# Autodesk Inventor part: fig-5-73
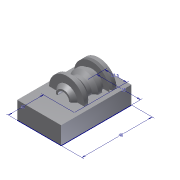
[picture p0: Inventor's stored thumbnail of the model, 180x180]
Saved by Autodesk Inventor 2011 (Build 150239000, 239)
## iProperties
Created: 2010-02
Part Number: fig-5-73
Document SubType Name: Modeling
Designer: CADSoft
Density: 1 g/cm^3
Author: CADSoft
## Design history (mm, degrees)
sketch "Sketch1"
  geometry: L1 (-12.5, 20)-(12.5, 20); L2 (12.5, 20)-(12.5, -20); L3 (12.5, -20)-(-12.5, -20); L4 (-12.5, -20)-(-12.5, 20); 1 further point
  constraints: 8 end point, 2 horizontal, 2 vertical
  dimensions: "d0" = 25 distance of L1.start L1.end; "d1" = 40 distance of L1.end L2.end; "d2" = 20 distance from line of L3 point (0, 0); "d3" = 12.5 distance from line of L4 point (0, 0)
extrude "Extrusion1" new body sketch "Sketch1" distance "d4" = 10; taper "d5" = 0 deg
sketch "Sketch2"
  geometry: L1 (-0.054, -20.11)-(-0.054, 21.401); L2 (3.173, 13.981)-(10.055, 13.981); L3 (10.055, 13.981)-(10.055, 11.83); L4 (10.055, 11.83)-(8.012, 10.969); L5 (8.012, 10.969)-(10.055, 10.001); L6 (10.055, 10.001)-(6.614, 10.001); L7 (6.614, 10.001)-(6.614, 7.851); L8 (6.614, 7.851)-(8.012, 7.851); L9 (8.012, 7.851)-(8.012, 5.7); L10 (8.012, 5.7)-(5.996, 4.073); L11 (5.996, 4.073)-(5.996, 1.828); L12 (5.996, 1.828)-(8.012, -0.069); L13 (8.012, -0.069)-(8.012, -2.151); L14 (8.012, -2.151)-(10.055, -2.151); L15 (10.055, -2.151)-(10.055, -4.194); L16 (10.055, -4.194)-(5.996, -4.194); L17 (5.996, -4.194)-(4.171, -6.134); L18 (4.171, -6.134)-(3.173, -6.134); L19 (3.173, -6.134)-(3.173, 13.981)
  constraints: 38 end point
revolve "Revolution1" sketch "Sketch2" stored, may be unused: angle "d6" = 180 deg
body "Solid1"
